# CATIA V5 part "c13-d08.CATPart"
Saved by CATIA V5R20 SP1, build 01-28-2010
Part number: Part1
Material "Alpine Fir": density 500 kg/m3, Young's modulus 1.7e+10 Pa, Poisson ratio 0.45, thermal expansion 3.75e-06 1/K
Bounding box of the stored display mesh (mm): x -163 to 95, y -77.362 to 77.362, z -85 to 85
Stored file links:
  D:\v5_r20\psrt_files_downloaded\c13-catia-v5r20-prt\c13-catia-v5r20-figr-13-32 & 33\c13-d08.CATPart
  C:\Program Files (x86)\Dassault Systemes\B20\intel_a\startup\materials\Catalog.CATMaterial
  C:\Program Files (x86)\Dassault Systemes\B20\intel_a\startup\materials\alpin_fir.jpg
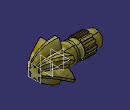
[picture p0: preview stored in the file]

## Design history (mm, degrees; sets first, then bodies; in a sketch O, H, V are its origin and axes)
Set1
  Plane1: type Offset, RefPlane face of Shaft1, Offset 45, reversed
  Plane2: type Offset, RefPlane Plane1, Offset 50, reversed
Body1 (main body), material "Alpine Fir"
  Sketch1 on zx-plane, origin (0, 0, 0), H (-1, 0, 0), V (0, 0, 1)
    axis line L1 (0, 0) -> (170, 0)
    line L2 (0, 0) -> (0, -45)
    point P2 (0, -45)
    line L3 (0, -45) -> (5, -45)
    point P3 (5, -45)
    line L4 (5, -45) -> (5, -39)
    line L5 (5, -39) -> (51, -39)
    line L6 (51, -39) -> (51, -38)
    point P6 (51, -38)
    line L7 (51, -38) -> (61, -38)
    point P7 (61, -38)
    line L8 (61, -38) -> (61, -36)
    point P8 (61, -36)
    arc A1 centre (72, -36) radius 11 from (61, -36) to (83, -36) cw
    point P10 (83, -36)
    line L9 (83, -36) -> (131, -36)
    line L10 (131, -36) -> (131, -32.5)
    line L11 (131, -32.5) -> (163, -32.5)
    line L12 (163, -32.5) -> (163, 0)
    point P14 (163, 0)
    line L13 (163, 0) -> (0, 0)
    "Radius" L11 L1 = 32.5
    "Radius" L9 L1 = 36
    "Radius" P7 L1 = 38
    "Radius" L5 L1 = 39
    "Radius" P3 L1 = 45
    length L11 = 32
    length L9 = 48
    distance P10 P8 = 22
    distance P7 P6 = 10
    length L5 = 46
    distance P3 P2 = 5
    horizontal: L1 H, L3 H, L5 H, L7 H, L9 H, L11 H, L13 H
    vertical: L2 V, L4 V, L6 V, L8 V, L12 V, L10 V
    tangency: A1 L8
    coincidence: P14 L1
  Shaft1: profile Sketch1, axis Sketch1.L1, angle 360
  Sketch2 on face of Shaft1, origin (-131, 0, 0), H (0, -1, 0), V (0, 0, 1)
    projected circle E1 centre (0, 0) radius 36 from edge [face of Shaft1 | face of Shaft1]
    projected arc E2 centre (0, 0) radius 36 from (5, 35.6511) to (-5, 35.6511) ccw from edge [face of Shaft1 | face of Shaft1]
    axis line L1 (0, 0) -> (0, 17.1744)
    point P2 (-5, 35.6511)
    line L2 (-5, 35.6511) -> (-5, 40.6511)
    point P3 (-5, 40.6511)
    line L3 (-5, 40.6511) -> (0, 40.6511)
    point P4 (0, 40.6511)
    point P5 (0, 40.6511)
    point P6 (5, 40.6511)
    line L4 (5, 40.6511) -> (0, 40.6511)
    point P7 (5, 35.6511)
    line L5 (5, 35.6511) -> (5, 40.6511)
    length L5 = 5
    distance L5 L2 = 10
    vertical: L1 V, L2 V
    coincidence: P2 E1, P4 L1, P4 P5
    horizontal: L3 H
    symmetry: P4 P5 L1, P3 P6 L1, L3 L4 L1, P2 P7 L1, L2 L5 L1
  Pad1: profile Sketch2, direction (1, 0, 0), length 48
  CircPattern1: of Pad1, instances 13, angular step 27.6923 {= 360.0*1 deg/CircPattern1.AngularNumber}, axis from face of Shaft1
  Loft1: solid, Sections (Sketch5; Sketch4; Sketch3)
  Sketch3 on Plane2, origin (95, 0, 0), H (0, -1, 0), V (0, 0, 1)
    construction line L1 through (0, 0) direction (1, 0)
    construction line L2 through (0, 0) direction (0, 1)
    arc A1 centre (23.3627, 6.7195) radius 24.375 from (13.5018, 29.0108) to (2.0971, 18.6324) ccw
    line L3 (18.3732, 26.1983) -> (13.5018, 29.0108)
    arc A2 centre (-5.8621, 23.5924) radius 24.375 from (15.0875, 11.1324) to (18.3732, 26.1983) ccw
    arc A3 centre (0, 0) radius 18.75 from (17.1847, 7.5) to (15.0875, 11.1324) ccw
    arc A4 centre (17.5006, -16.873) radius 24.375 from (31.875, 2.8125) to (17.1847, 7.5) ccw
    line L4 (31.875, -2.8125) -> (31.875, 2.8125)
    arc A5 centre (17.5006, 16.873) radius 24.375 from (17.1847, -7.5) to (31.875, -2.8125) ccw
    arc A6 centre (0, 0) radius 18.75 from (15.0875, -11.1324) to (17.1847, -7.5) ccw
    arc A7 centre (-5.8621, -23.5924) radius 24.375 from (18.3732, -26.1983) to (15.0875, -11.1324) ccw
    line L5 (13.5018, -29.0108) -> (18.3732, -26.1983)
    arc A8 centre (23.3627, -6.7195) radius 24.375 from (2.0971, -18.6324) to (13.5018, -29.0108) ccw
    arc A9 centre (0, 0) radius 18.75 from (-2.0971, -18.6324) to (2.0971, -18.6324) ccw
    arc A10 centre (-23.3627, -6.7195) radius 24.375 from (-13.5018, -29.0108) to (-2.0971, -18.6324) ccw
    line L6 (-18.3732, -26.1983) -> (-13.5018, -29.0108)
    arc A11 centre (5.8621, -23.5924) radius 24.375 from (-15.0875, -11.1324) to (-18.3732, -26.1983) ccw
    arc A12 centre (0, 0) radius 18.75 from (-17.1847, -7.5) to (-15.0875, -11.1324) ccw
    arc A13 centre (-17.5006, 16.873) radius 24.375 from (-31.875, -2.8125) to (-17.1847, -7.5) ccw
    line L7 (-31.875, 2.8125) -> (-31.875, -2.8125)
    arc A14 centre (-17.5006, -16.873) radius 24.375 from (-17.1847, 7.5) to (-31.875, 2.8125) ccw
    arc A15 centre (0, 0) radius 18.75 from (-15.0875, 11.1324) to (-17.1847, 7.5) ccw
    arc A16 centre (5.8621, 23.5924) radius 24.375 from (-18.3732, 26.1983) to (-15.0875, 11.1324) ccw
    line L8 (-13.5018, 29.0108) -> (-18.3732, 26.1983)
    arc A17 centre (-23.3627, 6.7195) radius 24.375 from (-2.0971, 18.6324) to (-13.5018, 29.0108) ccw
    arc A18 centre (0, 0) radius 18.75 from (2.0971, 18.6324) to (-2.0971, 18.6324) ccw
  Sketch4 on Plane1, origin (45, 0, 0), H (0, -1, 0), V (0, 0, 1)
    construction line L1 through (0, 0) direction (0.9659, -0.2588)
    construction line L2 through (0, 0) direction (0.2588, 0.9659)
    arc A1 centre (0, 0) radius 37.5 from (5.5935, -37.0805) to (13.6962, -34.9094) ccw
    arc A2 centre (-41.655, -25.0745) radius 48.75 from (-11.0664, -63.0336) to (5.5935, -37.0805) ccw
    arc A3 centre (48.6115, -0.8876) radius 48.75 from (13.6962, -34.9094) to (41.1006, -49.0555) ccw
    line L3 (49.0555, -41.1006) -> (41.1006, -49.0555)
    arc A4 centre (0.8876, -48.6115) radius 48.75 from (49.0555, -41.1006) to (34.9094, -13.6962) ccw
    arc A5 centre (0, 0) radius 37.5 from (34.9094, -13.6962) to (37.0805, -5.5935) ccw
    arc A6 centre (25.0745, 41.655) radius 48.75 from (37.0805, -5.5935) to (63.0336, 11.0664) ccw
    line L4 (60.1219, 21.933) -> (63.0336, 11.0664)
    arc A7 centre (42.5426, -23.5371) radius 48.75 from (60.1219, 21.933) to (29.3159, 23.3843) ccw
    arc A8 centre (0, 0) radius 37.5 from (29.3159, 23.3843) to (23.3843, 29.3159) ccw
    arc A9 centre (-23.5371, 42.5426) radius 48.75 from (23.3843, 29.3159) to (21.933, 60.1219) ccw
    line L5 (11.0664, 63.0336) -> (21.933, 60.1219)
    arc A10 centre (41.655, 25.0745) radius 48.75 from (11.0664, 63.0336) to (-5.5935, 37.0805) ccw
    arc A11 centre (0, 0) radius 37.5 from (-5.5935, 37.0805) to (-13.6962, 34.9094) ccw
    arc A12 centre (-48.6115, 0.8876) radius 48.75 from (-13.6962, 34.9094) to (-41.1006, 49.0555) ccw
    line L6 (-49.0555, 41.1006) -> (-41.1006, 49.0555)
    arc A13 centre (-0.8876, 48.6115) radius 48.75 from (-49.0555, 41.1006) to (-34.9094, 13.6962) ccw
    arc A14 centre (0, 0) radius 37.5 from (-34.9094, 13.6962) to (-37.0805, 5.5935) ccw
    arc A15 centre (-25.0745, -41.655) radius 48.75 from (-37.0805, 5.5935) to (-63.0336, -11.0664) ccw
    line L7 (-60.1219, -21.933) -> (-63.0336, -11.0664)
    arc A16 centre (-42.5426, 23.5371) radius 48.75 from (-60.1219, -21.933) to (-29.3159, -23.3843) ccw
    arc A17 centre (0, 0) radius 37.5 from (-29.3159, -23.3843) to (-23.3843, -29.3159) ccw
    arc A18 centre (23.5371, -42.5426) radius 48.75 from (-23.3843, -29.3159) to (-21.933, -60.1219) ccw
    line L8 (-11.0664, -63.0336) -> (-21.933, -60.1219)
  Sketch5 on face of Shaft1, origin (0, 0, 0), H (0, 1, 0), V (0, 0, 1)
    arc A1 centre (44.9945, 46.6682) radius 65 from (-20, 45.8258) to (-7.5, 85) cw
    point P1 (-7.5, 85)
    point P2 (7.5, 85)
    arc A2 centre (-44.9945, 46.6682) radius 65 from (20, 45.8258) to (7.5, 85) ccw
    line L1 (-7.5, 85) -> (7.5, 85)
    point P3 (7.5, 85)
    point P4 (20, 45.8258)
    point P5 (-20, 45.8258)
    point P6 (0, 0)
    arc A3 centre (0, 0) radius 50 from (29.6863, 40.2334) to (20, 45.8258) ccw
    arc A4 centre (-17.9186, 62.3005) radius 65 from (-49.6863, 5.5924) to (-77.3622, 36.0048) cw
    arc A5 centre (-62.9132, -15.6323) radius 65 from (-29.6863, 40.2334) to (-69.8622, 48.9952) ccw
    line L2 (-77.3622, 36.0048) -> (-69.8622, 48.9952)
    arc A6 centre (-62.9132, 15.6323) radius 65 from (-29.6863, -40.2334) to (-69.8622, -48.9952) cw
    arc A7 centre (-17.9186, -62.3005) radius 65 from (-49.6863, -5.5924) to (-77.3622, -36.0048) ccw
    line L3 (-69.8622, -48.9952) -> (-77.3622, -36.0048)
    arc A8 centre (-44.9945, -46.6682) radius 65 from (20, -45.8258) to (7.5, -85) cw
    arc A9 centre (44.9945, -46.6682) radius 65 from (-20, -45.8258) to (-7.5, -85) ccw
    line L4 (7.5, -85) -> (-7.5, -85)
    arc A10 centre (17.9186, -62.3005) radius 65 from (49.6863, -5.5924) to (77.3622, -36.0048) cw
    arc A11 centre (62.9132, 15.6323) radius 65 from (29.6863, -40.2334) to (69.8622, -48.9952) ccw
    line L5 (77.3622, -36.0048) -> (69.8622, -48.9952)
    arc A12 centre (62.9132, -15.6323) radius 65 from (29.6863, 40.2334) to (69.8622, 48.9952) cw
    arc A13 centre (17.9186, 62.3005) radius 65 from (49.6863, 5.5924) to (77.3622, 36.0048) ccw
    line L6 (69.8622, 48.9952) -> (77.3622, 36.0048)
    arc A14 centre (0, 0) radius 50 from (-49.6863, 5.5924) to (-49.6863, -5.5924) ccw
    arc A15 centre (0, 0) radius 50 from (-29.6863, -40.2334) to (-20, -45.8258) ccw
    arc A16 centre (0, 0) radius 50 from (20, -45.8258) to (29.6863, -40.2334) ccw
    arc A17 centre (0, 0) radius 50 from (49.6863, -5.5924) to (49.6863, 5.5924) ccw
    arc A18 centre (0, 0) radius 50 from (-20, 45.8258) to (-29.6863, 40.2334) ccw
    distance P4 P5 = 40
    radius A2 = 65
    length L1 = 15
    distance P6 L1 = 85
    radius A3 = 50
    symmetry: P1 P2 V, A1 A2 V, P4 P5 V
    coincidence: P3 A2, P6 O, P5 A3, A3 A14, A14 A15, A15 A16, A16 A17, A3 A18
    horizontal: L1 H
